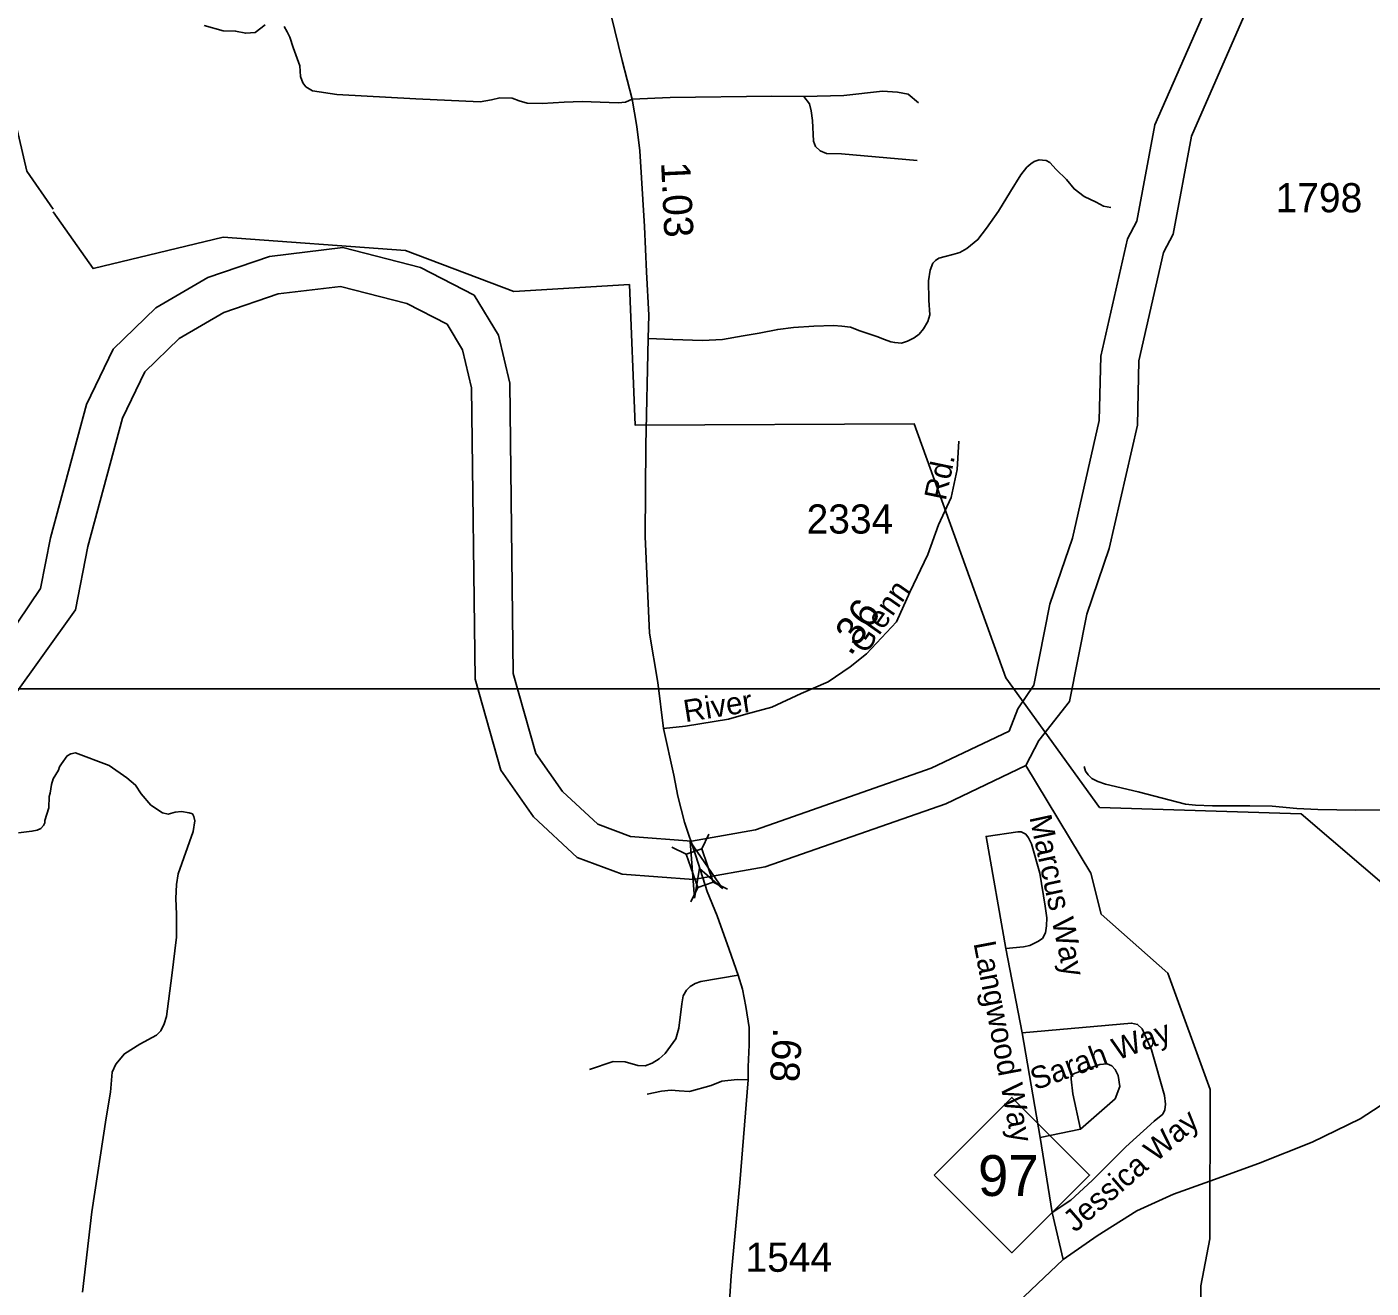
# Model space of a CAD drawing. Extents: x 2220236 to 2384410, y 720751 to 894131.
# Drawn here: x 2333123 to 2338888, y 782476 to 787885 of the extents above; entities that cross this region are included whole.
import ezdxf

# ---------------------------------------------------------------- set-up
doc = ezdxf.new("R2010")
doc.units = 0
for name, color, linetype in [('Exist Hydrographic Creek Single Shore', 7, 'Continuous'), ('Exist Hydrographic River Shore', 7, 'Continuous'), ('Exist Road Non-System Type 51', 7, 'Continuous'), ('Exist Road Non-System Type 51 Label', 7, 'Continuous'), ('Exist Road Primary NC Attributed', 7, 'Continuous'), ('Exist Road Primary NC Shield CELL', 7, 'Continuous'), ('Exist Road Primary NC Shield Number Label', 7, 'Continuous'), ('Exist Road Secondary Mileage Hundredths English Label', 7, 'Continuous'), ('Exist Road Secondary Structure Standard Bridge Attributed CELL', 7, 'Continuous'), ('Exist Road Secondary Structure Standard Bridge CELL', 7, 'Continuous'), ('Exist Road Secondary Type 51 Attributed', 7, 'Continuous'), ('Exist Road Secondary Type 51 Label', 7, 'Continuous'), ('Exist Road Secondary Type 51 Number Label', 7, 'Continuous'), ('Exist Utilities Electrical Transmission Line', 7, 'Continuous'), ('Map Preparation Inset Cut Line', 7, 'Continuous')]:
    doc.layers.add(name, color=color, linetype=linetype)

msp = doc.modelspace()

# ---------------------------------------------------------------- linework, layer by layer
at = {"layer": 'Exist Hydrographic Creek Single Shore'}
msp.add_lwpolyline([(2338161.2, 782151.7), (2338157.3, 782486.3), (2338196.3, 782688.1), (2338197.3, 783328.1), (2338016.3, 783826.2), (2337730.2, 784080.4), (2337686.3, 784255.8), (2337406.5, 784717)], dxfattribs=at)
at = {"layer": 'Exist Hydrographic River Shore'}
for points in [[(2337335.9, 784865.1), (2337372.7, 784960.1), (2337441.5, 785062.1), (2337510, 785408.7), (2337607.3, 785692.8), (2337722.4, 786197.3), (2337728.4, 786473.2), (2337842.8, 786975.6), (2337883, 787051.4), (2337960.3, 787465), (2338211.6, 788038.7), (2338430.3, 788305.4), (2338707.4, 788526.9), (2339767.8, 789070.1), (2340542.6, 789418.3), (2340665.7, 789499.9), (2340992, 789572.6), (2341431.5, 789620), (2341905.1, 789744.5), (2342531.1, 789800.1), (2342949.9, 789807.3)], [(2337406.5, 784717), (2337463, 784824.3), (2337594.8, 784991.5), (2337668.7, 785366.1), (2337765.3, 785647.8), (2337886.1, 786177.1), (2337892, 786453), (2337997.9, 786917.9), (2338039.6, 786996.5), (2338118.1, 787416.3), (2338352.8, 787952.1), (2338546.3, 788188), (2338797, 788388.5), (2339838.8, 788922.2), (2340622.1, 789274.2), (2340731, 789346.4), (2341018.7, 789410.5), (2341461.3, 789458.2), (2341933.4, 789582.3), (2342539.8, 789636.2), (2342952.7, 789643.2)], [(2337335.9, 784865.1), (2337000.9, 784705.5), (2336248.4, 784441.7), (2335974.1, 784393.4), (2335711.9, 784412.9), (2335571, 784465.3), (2335420.4, 784605.5), (2335306.4, 784768.9), (2335209.1, 785111.7), (2335194, 786356.5), (2335145, 786563.1), (2335041.3, 786735), (2334811.5, 786853.2), (2334478.6, 786938.6), (2334163.7, 786900.8), (2333899, 786809.8), (2333676.1, 786680.7), (2333493.4, 786502.4), (2333378.9, 786265), (2333224.2, 785694.1), (2333181.2, 785476.6)], [(2337406.5, 784717), (2337063.5, 784553.6), (2336290, 784282.5), (2335982.3, 784228.2), (2335676.5, 784251.1), (2335483.2, 784323), (2335295.9, 784497.3), (2335156.1, 784697.6), (2335045.4, 785088), (2335030.2, 786336.4), (2334991.3, 786500.3), (2334924.9, 786610.4), (2334752.8, 786698.8), (2334467.6, 786772), (2334200.6, 786740), (2333967.4, 786659.9), (2333776.1, 786549), (2333628.6, 786405.2), (2333533.2, 786207.4), (2333384, 785656.7), (2333331.5, 785385.3)], [(2330163, 784084.9), (2330733.1, 784610.8), (2330993, 784731.7), (2331481.8, 784832.8), (2332572.7, 784909.9), (2332829.5, 785019), (2332935.7, 785114), (2333181.2, 785476.6)], [(2330270, 783969.1), (2330825, 784472.6), (2331044.9, 784574.9), (2331504.3, 784670), (2332611.6, 784748.2), (2332918.7, 784878.6), (2333058.6, 785003.8), (2333331.5, 785385.3)]]:
    msp.add_lwpolyline(points, dxfattribs=at)
at = {"layer": 'Exist Road Non-System Type 51'}
for p, q in [((2337391.1, 783571.2), (2337320.8, 783932.2)), ((2337468.5, 783122.3), (2337391.1, 783571.2)), ((2337641.9, 783158.4), (2337468.5, 783122.3)), ((2337520.2, 782801.1), (2337468.5, 783122.3)), ((2337567, 782598.6), (2337520.2, 782801.1))]:
    msp.add_line(p, q, dxfattribs=at)
for points in [[(2334145.5, 787893.6), (2334101.5, 787860.6), (2334062, 787857.3), (2334018.1, 787867.2), (2333965.4, 787868.3), (2333884.1, 787891.4)], [(2335719.5, 787574.4), (2335689.9, 787562.3), (2335659.1, 787559), (2335504.3, 787565.6), (2335427.5, 787562.3), (2335333, 787556.8), (2335268.8, 787557.3), (2335234.7, 787568.3), (2335204, 787579.3), (2335151.3, 787580.4), (2335115.1, 787572.7), (2335066.7, 787563.9), (2334791.1, 787576), (2334452.9, 787594.7), (2334348.6, 787611.2), (2334320.1, 787627.7), (2334306.9, 787645.2), (2334295.9, 787672.7), (2334293.7, 787717.8), (2334265.2, 787796.9), (2334250.9, 787840.8), (2334238.8, 787863.9), (2334226.7, 787885.9)], [(2336947.3, 787558.5), (2336902.9, 787595.9), (2336856.7, 787605.4), (2336792.8, 787608.6), (2336627.1, 787590.3), (2336455.8, 787585.9)], [(2336455.8, 787585.9), (2336317.4, 787588.1), (2335882.6, 787582.6), (2335719.5, 787574.4)], [(2336941.1, 787311.2), (2336762.1, 787327.7), (2336616.1, 787340.9), (2336552.4, 787342), (2336525, 787353), (2336505.2, 787371.7), (2336496.4, 787394.7), (2336492, 787483.7), (2336486.5, 787525.5), (2336478.8, 787555.1), (2336455.8, 787585.9)], [(2335787.6, 786548), (2335893.8, 786544.1), (2336020.8, 786540.4), (2336106.1, 786544.1), (2336195.2, 786559.3), (2336263.4, 786570.7), (2336343, 786587.8), (2336411.2, 786595.3), (2336498.4, 786601), (2336581.8, 786604.8), (2336617.8, 786601), (2336655.7, 786597.2), (2336695.5, 786582.1), (2336767.5, 786557.4), (2336801.6, 786544.1), (2336828.2, 786534.7), (2336845.2, 786530.9), (2336873.7, 786529), (2336900.2, 786536.6), (2336928.6, 786551.7), (2336949.5, 786566.9), (2336968.4, 786589.7), (2336987.4, 786621.9), (2336995, 786650.3), (2336991.2, 786712.9), (2336989.3, 786796.4), (2336996.9, 786841.9), (2337008.2, 786872.2), (2337019.6, 786883.6), (2337034.8, 786893.1), (2337061.3, 786900.7), (2337093.5, 786908.3), (2337123.8, 786917.7), (2337154.2, 786934.8), (2337201.5, 786972.7), (2337238.5, 787021.1), (2337289.7, 787095.1), (2337340.8, 787178.5), (2337386.3, 787250.6), (2337411, 787282.8), (2337428, 787298), (2337443.2, 787307.5), (2337464, 787315.1), (2337479.2, 787313.2), (2337494.4, 787311.3), (2337509.5, 787303.7), (2337537.9, 787273.3), (2337581.5, 787229.7), (2337613.8, 787189.9), (2337657.3, 787157.6), (2337708.5, 787133), (2337740.7, 787115.9), (2337771.1, 787110.2)], [(2333087.1, 784428.7), (2333144.9, 784435.2), (2333166.9, 784439.5), (2333182.8, 784447.6), (2333194.7, 784459.9), (2333200.6, 784471.9), (2333200.4, 784481.9), (2333217.8, 784536), (2333219.2, 784583.9), (2333223.1, 784598.1), (2333228.7, 784636.1), (2333236.5, 784660), (2333258.1, 784698), (2333262.7, 784711.1), (2333271.8, 784724.3), (2333296.1, 784759.5), (2333312, 784767.8), (2333332, 784772), (2333476.5, 784717.7), (2333551.3, 784664.7), (2333589.6, 784633.1), (2333613.9, 784595.4), (2333654.5, 784547.9), (2333704.9, 784514.5), (2333728.9, 784508.9), (2333759, 784517.1), (2333786.9, 784519.5), (2333818.9, 784514), (2333832.9, 784510.1), (2333839, 784498.2), (2333843.3, 784480.2), (2333835.8, 784434.2), (2333772.2, 784253.4), (2333764.6, 784207.4), (2333761.3, 784147.3), (2333764.1, 784079.3), (2333765.2, 783981.4), (2333745.3, 783817.3), (2333721.5, 783641), (2333711.8, 783609), (2333698.2, 783578.9), (2333678.4, 783560.6), (2333606.9, 783521.7), (2333541.4, 783481), (2333504, 783436.5), (2333488.3, 783402.4), (2333481.5, 783316.3), (2333462.7, 783206.1), (2333401.5, 782803.4), (2333361.8, 782459.1)], [(2337656.7, 784713.7), (2337663.3, 784692.9), (2337674.3, 784677.5), (2337690.8, 784662.1), (2337716, 784648.9), (2337749, 784636.8), (2337888.4, 784603.9), (2338091.6, 784551.1), (2338135.5, 784546.7), (2338208, 784544.5), (2338368.3, 784544.5), (2338463.8, 784542.3), (2338569.2, 784532.5), (2338659.3, 784528.1), (2338822.9, 784525.9), (2338985.4, 784527), (2339153.4, 784528.1), (2339391.7, 784529.2), (2339565.2, 784533.6), (2339722.2, 784537.9), (2339796.9, 784537.9), (2339822.1, 784535.7), (2339843, 784529.2), (2339864.4, 784513.2)], [(2337320.8, 783932.2), (2337236.9, 784413), (2337372.8, 784432.8), (2337386.9, 784432.5), (2337406.8, 784423.2), (2337419, 784407.2), (2337431.3, 784381.3), (2337466.8, 784255.9), (2337490.4, 784114.2), (2337497.1, 784064.3), (2337495.5, 784030.2), (2337491.9, 784000.3), (2337478.3, 783976.1), (2337458.4, 783961.9), (2337424.5, 783945.5), (2337396.7, 783939.1), (2337320.8, 783932.2)], [(2336173, 783817.7), (2336012.8, 783790.6), (2335988.9, 783782.2), (2335967.2, 783769.9), (2335951.3, 783753.9), (2335938.1, 783729.8), (2335931.5, 783695.8), (2335918.8, 783590.8), (2335906, 783545.3), (2335860.7, 783482.9), (2335834.8, 783459.5), (2335804.1, 783440.8), (2335774.4, 783429.9), (2335743.7, 783431), (2335688.8, 783446.3), (2335637.2, 783447.4), (2335535.6, 783413)], [(2337391.1, 783571.2), (2337860.4, 783612.9), (2337886.5, 783607.2), (2337906.7, 783587.4), (2337945.8, 783498), (2338002.2, 783302.6), (2338006.5, 783264.7), (2338002.9, 783240.6), (2337995, 783222.7), (2337957.4, 783192.1), (2337836, 783082.1), (2337691.1, 782937.1), (2337600, 782853.6), (2337520.2, 782801.1)], [(2337641.9, 783158.4), (2337790.3, 783288.1), (2337809.7, 783340.4), (2337803.2, 783388.3), (2337790.7, 783414), (2337776.7, 783429.8), (2337756.5, 783437.6), (2337724.6, 783435.3), (2337619.1, 783398), (2337607.1, 783391.9), (2337601.3, 783383.9), (2337601.4, 783371.9), (2337608.1, 783309.9), (2337641.9, 783158.4)], [(2336216.4, 783370), (2336169.8, 783370.6), (2336104, 783363.8), (2336058.2, 783345.3), (2335964.6, 783320), (2335920.5, 783321.6), (2335886.5, 783325.3), (2335844.5, 783320.7), (2335782.8, 783308)]]:
    msp.add_lwpolyline(points, dxfattribs=at)
at = {"layer": 'Exist Road Primary NC Attributed'}
msp.add_lwpolyline([(2336287.2, 781362), (2336544.2, 781621.3), (2336891.7, 781957), (2337456.7, 782494.8), (2337567, 782598.6), (2337713.1, 782700.8), (2337883.8, 782806.9), (2338040.8, 782879.4), (2338195.7, 782935.4), (2338404.3, 783010.1), (2338635.4, 783101.9), (2338840.8, 783201.9), (2339012.1, 783313.9), (2339172.4, 783440.3), (2339292.1, 783562.3), (2339374.4, 783655.6), (2339424.4, 783719.9)], dxfattribs=at)
at = {"layer": 'Exist Road Primary NC Shield CELL'}
msp.add_lwpolyline([(2337014.7, 782961.1), (2337347.7, 783294), (2337680.7, 782961.1), (2337347.7, 782628.1)], close=True, dxfattribs=at)
at = {"layer": 'Exist Road Secondary Structure Standard Bridge Attributed CELL'}
msp.add_lwpolyline([(2335986.8, 784148), (2335967.4, 784391.1), (2336105.7, 784190.2), (2336008.2, 784276.2)], close=True, dxfattribs=at)
at = {"layer": 'Exist Road Secondary Structure Standard Bridge CELL'}
for p, q in [((2336047.5, 784422.2), (2336017.4, 784360.2)), ((2335888.6, 784367.3), (2335950.6, 784337.1)), ((2336001.2, 784194.7), (2335971, 784132.7)), ((2336066.4, 784217.3), (2336128.4, 784187.1))]:
    msp.add_line(p, q, dxfattribs=at)
msp.add_lwpolyline([(2336017.4, 784360.2), (2336066.7, 784217.4), (2336000, 784194.3), (2335950.6, 784337.1)], close=True, dxfattribs=at)
at = {"layer": 'Exist Road Secondary Type 51 Attributed'}
for points in [[(2335852.8, 784875.8), (2335828.8, 785073.9), (2335792.9, 785285.4), (2335774, 785699.1), (2335777.3, 786090.9), (2335787.6, 786548), (2335789.8, 786648.1), (2335781, 786834.9), (2335772.2, 787028.3), (2335751.4, 787353.5), (2335739.3, 787457.9), (2335719.5, 787574.4), (2335675.6, 787740.3), (2335565.3, 788192.4), (2335493.9, 788474.7), (2335376.9, 788931.3), (2335351.7, 789037.9), (2335331.9, 789113.7), (2335323.1, 789136.8), (2335304.5, 789185.1), (2335262.7, 789257.7), (2335140.9, 789420.3), (2334696.7, 789915.3), (2334649.4, 789987.7)], [(2335852.8, 784875.8), (2335947.4, 784886.1), (2336132.5, 784915.7), (2336206.5, 784937.9), (2336317.6, 784967.6), (2336443.1, 785026.2), (2336559.8, 785075.7), (2336654.4, 785140.3), (2336723.5, 785195.7), (2336852.7, 785334.1), (2336910.3, 785461), (2336986.4, 785622.5), (2337032.5, 785749.3), (2337087.5, 785866.4), (2337112.9, 785986.3), (2337119.8, 786108.6)], [(2336021.8, 784235.2), (2335990.2, 784333.6), (2335943, 784474.2), (2335915.5, 784585.2), (2335898, 784676.4), (2335852.8, 784875.8)], [(2336287.2, 781362), (2336253.2, 781438.9), (2336211.3, 781583.8), (2336171.7, 781715.2), (2336142.2, 781846.7), (2336128.3, 781994.6), (2336120.9, 782180), (2336143.9, 782529.4), (2336181.3, 782927.2), (2336216.4, 783370), (2336216.4, 783424.9), (2336221.4, 783520), (2336220.3, 783593.6), (2336207.1, 783683.7), (2336192.1, 783757.8), (2336173, 783817.7), (2336135.2, 783928.1), (2336083.5, 784072.1), (2336040.7, 784176.5), (2336021.8, 784235.2)]]:
    msp.add_lwpolyline(points, dxfattribs=at)
at = {"layer": 'Exist Utilities Electrical Transmission Line'}
for points in [[(2332742.6, 788203.2), (2332986.2, 787850.1), (2333122.5, 787265.8), (2333236.2, 787103)], [(2333236.1, 787092.1), (2333406.9, 786848.1), (2333965.3, 786982.8), (2334747.5, 786926.3), (2335211.5, 786749.9), (2335707.1, 786779.8), (2335732.3, 786176.3), (2336927.8, 786182.7), (2337320.8, 785093.9), (2337723.3, 784536.9), (2338587.4, 784509.4), (2339379.3, 783833), (2339636.8, 783530.2), (2340026.3, 783554.9), (2340636.8, 783510.2), (2341087.9, 783395.8), (2341181.6, 782595), (2342038.7, 781811.7), (2342988.5, 780973.5), (2343263.3, 780726.8), (2344277.5, 780179.2), (2345408.3, 779577.1)]]:
    msp.add_lwpolyline(points, dxfattribs=at)
at = {"layer": 'Map Preparation Inset Cut Line'}
msp.add_lwpolyline([(2329807.7, 816974.9), (2370566.3, 816974.8), (2370566.3, 785046.7), (2329807.6, 785046.7), (2329807.7, 816974.9)], dxfattribs=at)
msp.add_lwpolyline([(2329807.7, 816974.9), (2370566.3, 816974.8), (2370566.3, 785046.7), (2329807.6, 785046.7), (2329807.7, 816974.9)], dxfattribs=at)

# ---------------------------------------------------------------- texts
at = {"layer": 'Exist Road Non-System Type 51 Label'}
for s, rotation, p in [('Marcus Way', 282.19482, (2337421.9, 784495.8)), ('Langwood Way', 280.77933, (2337182.5, 783955.5)), ('Sarah Way', 20.06487, (2337447.5, 783323.8)), ('Jessica Way', 40.99169, (2337618.8, 782712.2))]:
    msp.add_text(s, height=95, rotation=rotation, dxfattribs=at).set_placement(p)
at = {"layer": 'Exist Road Primary NC Shield Number Label'}
msp.add_text('97', height=175, dxfattribs=at).set_placement((2337201.9, 782871.3))
at = {"layer": 'Exist Road Secondary Mileage Hundredths English Label'}
for s, rotation, p in [('1.03', 272.60091, (2335842.8, 787304)), ('.36', 54.88029, (2336656, 785183.6)), ('.68', 266.22433, (2336324.7, 783594.9))]:
    msp.add_text(s, height=125, rotation=rotation, dxfattribs=at).set_placement(p)
at = {"layer": 'Exist Road Secondary Type 51 Label'}
for s, rotation, p in [('Rd.', 78.23779, (2337063.4, 785850)), ('Glenn', 54.88027, (2336720.9, 785191.6)), ('River', 9.09503, (2335947, 784902.7))]:
    msp.add_text(s, height=95, rotation=rotation, dxfattribs=at).set_placement(p)
at = {"layer": 'Exist Road Secondary Type 51 Number Label'}
for s, p in [('1798', (2338478.2, 787089.8)), ('2334', (2336467, 785712)), ('1544', (2336205, 782546.1))]:
    msp.add_text(s, height=125, dxfattribs=at).set_placement(p)

doc.saveas('drawing.dxf')
